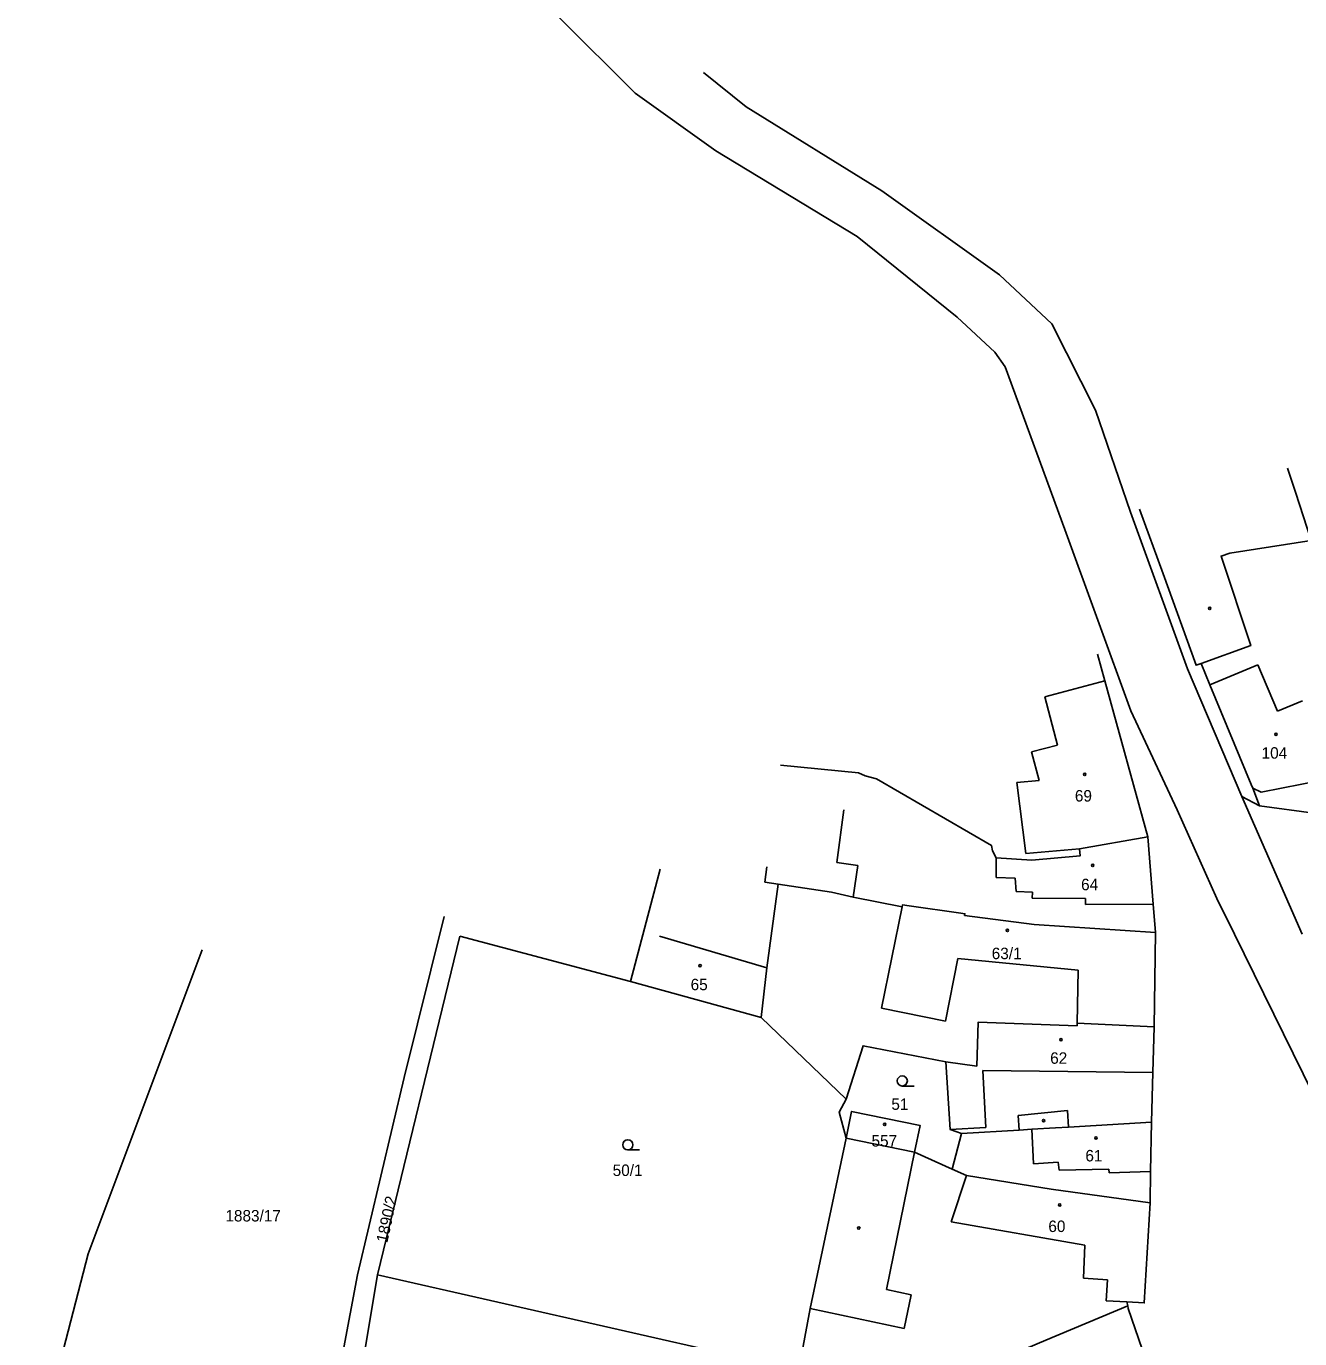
# Model space of a CAD drawing. Extents: x -793666 to -785424, y -1118958 to -1108761.
# Drawn here: x -788462.4 to -788273.7, y -1116448.6 to -1116254.2 of the extents above; entities that cross this region are included whole.
import ezdxf

# ---------------------------------------------------------------- set-up
doc = ezdxf.new("R2010")
doc.units = 0
for name, color, linetype in [('Hranice parcel', 7, 'Continuous'), ('Parcelní čísla', 7, 'Continuous'), ('Vnitřní kresba', 7, 'Continuous'), ('Značky budov', 7, 'Continuous'), ('Značky kultur', 7, 'Continuous')]:
    doc.layers.add(name, color=color, linetype=linetype)

msp = doc.modelspace()

# ---------------------------------------------------------------- linework, layer by layer
at = {"layer": 'Hranice parcel'}
for p, q in [((-788279.68, -1116369.68), (-788280.64, -1116367.02)), ((-788282.27, -1116368.25), (-788279.68, -1116369.68)), ((-788273.34, -1116388.69), (-788282.27, -1116368.25)), ((-788368.47, -1116379.05), (-788372.86, -1116395.67)), ((-788295.06, -1116388.44), (-788295.27, -1116402.38)), ((-788410.35, -1116439.11), (-788398.14, -1116388.94)), ((-788398.14, -1116388.94), (-788372.86, -1116395.67)), ((-788372.86, -1116395.67), (-788353.51, -1116401.01)), ((-788353.51, -1116401.01), (-788340.89, -1116413.11)), ((-788330.76, -1116420.96), (-788340.92, -1116418.9)), ((-788323.81, -1116418.19), (-788325.21, -1116423.46)), ((-788325.21, -1116423.46), (-788330.76, -1116420.96)), ((-788414.54, -1116464.14), (-788410.35, -1116439.11)), ((-788356.85, -1116451.26), (-788410.35, -1116439.11))]:
    msp.add_line(p, q, dxfattribs=at)
for points in [[(-788170.26, -1116598.58), (-788173.06, -1116593.82), (-788178.67, -1116584.28), (-788189.35, -1116571.03), (-788201.32, -1116556.56), (-788205.43, -1116550.12), (-788213.05, -1116535.35), (-788220.89, -1116518.34), (-788222.9, -1116517.41), (-788239.77, -1116479.02), (-788264.52, -1116427.02), (-788283.36, -1116388.67), (-788286.01, -1116383.37), (-788291.85, -1116370.26), (-788298.71, -1116355.56), (-788308.53, -1116328.7), (-788317.36, -1116304.62), (-788318.86, -1116302.45), (-788324.44, -1116297.25), (-788339.26, -1116285.32), (-788360.21, -1116272.65), (-788372.19, -1116264.09), (-788394.6, -1116241.69)], [(-788362.05, -1116261.04), (-788355.74, -1116266.13), (-788335.6, -1116278.55), (-788318.18, -1116290.98), (-788310.44, -1116298.27), (-788303.96, -1116311.03), (-788298.77, -1116326.17), (-788290.32, -1116349.37), (-788282.27, -1116368.25)], [(-788275.5, -1116319.65), (-788274.35, -1116323.18), (-788272.01, -1116330.34)], [(-788288.3, -1116348.55), (-788289.06, -1116348.82), (-788293.96, -1116335.28), (-788297.42, -1116325.73)], [(-788272.01, -1116330.34), (-788284.04, -1116332.23), (-788285.35, -1116332.67), (-788280.97, -1116345.92), (-788288.3, -1116348.55)], [(-788303.69, -1116347.2), (-788302.59, -1116351.13), (-788296.23, -1116374.27)], [(-788288.3, -1116348.55), (-788287.03, -1116351.72), (-788280.9, -1116366.49), (-788280.64, -1116367.02)], [(-788279.68, -1116369.68), (-788255.51, -1116372.91), (-788222.27, -1116376.2), (-788184.96, -1116374.64), (-788169.09, -1116371.97), (-788125.59, -1116364.93), (-788118.03, -1116366.65), (-788103.88, -1116370.26), (-788071.66, -1116376.73), (-788047.19, -1116381.42), (-788037.25, -1116382.67), (-788028.44, -1116382.62), (-788012.56, -1116381.23), (-787982.57, -1116375.12), (-787957.81, -1116369.21), (-787938.9, -1116364.93), (-787918.57, -1116359.78), (-787902.51, -1116353.37)], [(-788296.23, -1116374.27), (-788306.31, -1116376.03), (-788306.23, -1116377.05), (-788313.42, -1116377.68), (-788318.68, -1116377.37), (-788319.24, -1116376.3), (-788319.38, -1116375.51), (-788336.4, -1116365.67), (-788338.11, -1116365.19), (-788339.09, -1116364.79), (-788350.64, -1116363.64)], [(-788280.64, -1116367.02), (-788279.42, -1116367.61), (-788267.36, -1116365.28)], [(-788296.23, -1116374.27), (-788295.41, -1116384.24), (-788295.06, -1116388.44)], [(-788352.65, -1116378.69), (-788352.95, -1116380.95), (-788351, -1116381.24)], [(-788351, -1116381.24), (-788352.65, -1116393.65), (-788353.51, -1116401.01)], [(-788295.06, -1116388.44), (-788313.06, -1116387.22), (-788323.35, -1116385.88), (-788323.32, -1116385.63), (-788323.92, -1116385.54), (-788331.57, -1116384.48), (-788332.56, -1116384.34), (-788332.62, -1116384.64), (-788339.86, -1116383.2), (-788343.09, -1116382.43), (-788351, -1116381.24)], [(-788421.23, -1116481.16), (-788413.32, -1116439.14), (-788406.38, -1116409.89), (-788400.46, -1116386.05)], [(-788436.34, -1116390.99), (-788453.24, -1116436.02), (-788462.39, -1116471.52)], [(-788295.27, -1116402.38), (-788306.68, -1116401.87), (-788306.68, -1116402.23), (-788321.33, -1116401.68), (-788321.57, -1116408.22), (-788326.14, -1116407.58)], [(-788295.27, -1116402.38), (-788295.47, -1116409.17), (-788295.65, -1116416.54)], [(-788340.89, -1116413.11), (-788338.4, -1116405.19), (-788326.14, -1116407.58)], [(-788326.14, -1116407.58), (-788325.52, -1116417.59), (-788323.81, -1116418.19)], [(-788340.92, -1116418.9), (-788341.94, -1116415.05), (-788340.89, -1116413.11)], [(-788330.76, -1116420.96), (-788329.93, -1116417.02), (-788340.1, -1116414.93), (-788340.92, -1116418.9)], [(-788295.65, -1116416.54), (-788307.98, -1116417.25), (-788309.88, -1116417.36), (-788313.41, -1116417.57), (-788315.27, -1116417.68), (-788323.81, -1116418.19)], [(-788295.65, -1116416.54), (-788295.82, -1116423.81), (-788295.86, -1116428.45)], [(-788340.92, -1116418.9), (-788346.24, -1116444.12), (-788348.08, -1116453.93)], [(-788295.86, -1116428.45), (-788310.54, -1116426.43), (-788323.1, -1116424.41), (-788325.21, -1116423.46)], [(-788295.86, -1116428.45), (-788296.73, -1116443.28), (-788299.33, -1116443.15), (-788299.17, -1116443.74)], [(-788299.17, -1116443.74), (-788311.32, -1116448.82), (-788325.63, -1116454.87), (-788325.73, -1116454.15), (-788325.75, -1116453.97), (-788334.82, -1116453.91), (-788344.45, -1116454.29), (-788348.08, -1116453.93)], [(-788299.17, -1116443.74), (-788299.11, -1116444.14), (-788297.03, -1116450.12), (-788295.49, -1116454.27)]]:
    msp.add_lwpolyline(points, dxfattribs=at)
at = {"layer": 'Vnitřní kresba'}
for p, q in [((-788287.03, -1116351.72), (-788279.93, -1116348.75)), ((-788279.93, -1116348.75), (-788276.98, -1116355.65)), ((-788311.46, -1116353.49), (-788302.59, -1116351.13)), ((-788309.6, -1116360.65), (-788311.46, -1116353.49)), ((-788276.98, -1116355.65), (-788273.31, -1116354.12)), ((-788313.43, -1116361.65), (-788309.6, -1116360.65)), ((-788312.32, -1116365.88), (-788313.43, -1116361.65)), ((-788315.6, -1116366.19), (-788312.32, -1116365.88)), ((-788314.27, -1116376.72), (-788315.6, -1116366.19)), ((-788341.26, -1116370.26), (-788342.31, -1116378.04)), ((-788314.27, -1116376.72), (-788306.31, -1116376.03)), ((-788342.31, -1116378.04), (-788339.18, -1116378.47)), ((-788339.18, -1116378.47), (-788339.86, -1116383.2)), ((-788318.68, -1116377.37), (-788318.66, -1116380.26)), ((-788318.66, -1116380.26), (-788315.85, -1116380.39)), ((-788315.85, -1116380.39), (-788315.73, -1116382.35)), ((-788315.73, -1116382.35), (-788313.3, -1116382.44)), ((-788313.3, -1116382.44), (-788313.35, -1116383.31)), ((-788332.62, -1116384.64), (-788335.66, -1116399.64)), ((-788313.35, -1116383.31), (-788305.43, -1116383.39)), ((-788305.43, -1116383.39), (-788305.45, -1116384.25)), ((-788305.45, -1116384.25), (-788295.41, -1116384.24)), ((-788368.58, -1116388.97), (-788352.65, -1116393.65)), ((-788326.2, -1116401.55), (-788324.36, -1116392.25)), ((-788324.36, -1116392.25), (-788306.53, -1116393.99)), ((-788306.53, -1116393.99), (-788306.68, -1116401.87)), ((-788335.66, -1116399.64), (-788326.2, -1116401.55)), ((-788320.21, -1116417.3), (-788320.65, -1116408.86)), ((-788320.65, -1116408.86), (-788295.47, -1116409.17)), ((-788308.12, -1116414.8), (-788315.4, -1116415.51)), ((-788315.4, -1116415.51), (-788315.27, -1116417.68)), ((-788307.98, -1116417.25), (-788308.12, -1116414.8)), ((-788325.52, -1116417.59), (-788320.21, -1116417.3)), ((-788313.41, -1116417.57), (-788313.17, -1116422.67)), ((-788334.94, -1116441.32), (-788330.76, -1116420.96)), ((-788313.17, -1116422.67), (-788309.48, -1116422.45)), ((-788309.48, -1116422.45), (-788309.36, -1116423.65)), ((-788309.36, -1116423.65), (-788301.98, -1116423.46)), ((-788301.98, -1116423.46), (-788301.96, -1116424.03)), ((-788323.1, -1116424.41), (-788325.34, -1116431.29)), ((-788301.96, -1116424.03), (-788295.82, -1116423.81)), ((-788325.34, -1116431.29), (-788305.54, -1116434.76)), ((-788305.54, -1116434.76), (-788305.73, -1116439.61)), ((-788305.73, -1116439.61), (-788302.17, -1116439.88)), ((-788302.17, -1116439.88), (-788302.4, -1116443)), ((-788331.26, -1116442.08), (-788334.94, -1116441.32)), ((-788332.29, -1116447.08), (-788331.26, -1116442.08)), ((-788302.4, -1116443), (-788299.33, -1116443.15)), ((-788346.24, -1116444.12), (-788332.29, -1116447.08))]:
    msp.add_line(p, q, dxfattribs=at)
at = {"layer": 'Značky budov'}
for centre in [(-788287.03, -1116340.41), (-788277.22, -1116359.06), (-788305.55, -1116365.01), (-788304.38, -1116378.49), (-788317.01, -1116388.11), (-788362.54, -1116393.35), (-788309.09, -1116404.31), (-788335.2, -1116416.85), (-788311.65, -1116416.29), (-788303.9, -1116418.84), (-788309.27, -1116428.78), (-788339.03, -1116432.2)]:
    msp.add_circle(centre, 0.175, dxfattribs=at)
at = {"layer": 'Značky kultur'}
for p, q in [((-788332.59, -1116411.16), (-788330.84, -1116411.16)), ((-788373.26, -1116420.62), (-788371.51, -1116420.62))]:
    msp.add_line(p, q, dxfattribs=at)
for centre in [(-788332.59, -1116410.41), (-788373.26, -1116419.87)]:
    msp.add_circle(centre, 0.75, dxfattribs=at)

# ---------------------------------------------------------------- texts
at = {"layer": 'Parcelní čísla'}
for s, p in [('104', (-788279.35, -1116362.67)), ('69', (-788307.02, -1116369.02)), ('64', (-788306.1, -1116382.16)), ('63/1', (-788319.34, -1116392.37)), ('65', (-788363.95, -1116396.97)), ('62', (-788310.68, -1116407.87)), ('51', (-788334.21, -1116414.69)), ('557', (-788337.15, -1116420.13)), ('61', (-788305.46, -1116422.33)), ('50/1', (-788375.5, -1116424.49)), ('1883/17', (-788432.88, -1116431.23)), ('60', (-788310.95, -1116432.79))]:
    msp.add_text(s, height=1.7, dxfattribs=at).set_placement(p)
msp.add_text('1890/2', height=1.7, rotation=78, dxfattribs=at).set_placement((-788408.89, -1116434.47))

doc.saveas('drawing.dxf')
